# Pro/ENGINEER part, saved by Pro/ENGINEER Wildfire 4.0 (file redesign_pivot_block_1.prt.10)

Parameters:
  METRIC = "NO"

Other parameters: PITCH, DRILL_POINT_ANGLE, DRILL_DEPTH, DRILL_DIAMETER, THREAD_DIAMETER, THREADS_PER_INCH, THREAD_DEPTH, THREAD_LENGTH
